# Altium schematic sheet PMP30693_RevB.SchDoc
size 431 x 279 mm; Date: Not shown in title block; ApprovedBy: Not shown in title block; CheckedBy: Not shown in title block; Author: Not shown in title block; CompanyName: Not shown in title block; Engineer: Not shown in title block; Organization: Not shown in title block; Address1: Not shown in title block; Address2: Not shown in title block; Address3: Not shown in title block; Address4: Not shown in title block; DocumentNumber: 2; Revision: Use project parameter SCH_Rev; SheetNumber: 2; SheetTotal: 3; PageSetup: Record=PageOptions¦CenterHorizontal=True¦CenterVertical=True¦PrintScale=1.00¦XCorrection=1.00¦YCorrection=1.00¦PrintKind=0¦BorderSize=5000000¦LeftOffset=0¦BottomOffset=0¦Orientation=2¦PaperLength=1000¦PaperWidth=1000¦Scale=100¦PaperSource=15¦PrintQuality=600¦MediaType=1¦DitherType=10¦PaperKind=Letter¦PrintScaleMode=1
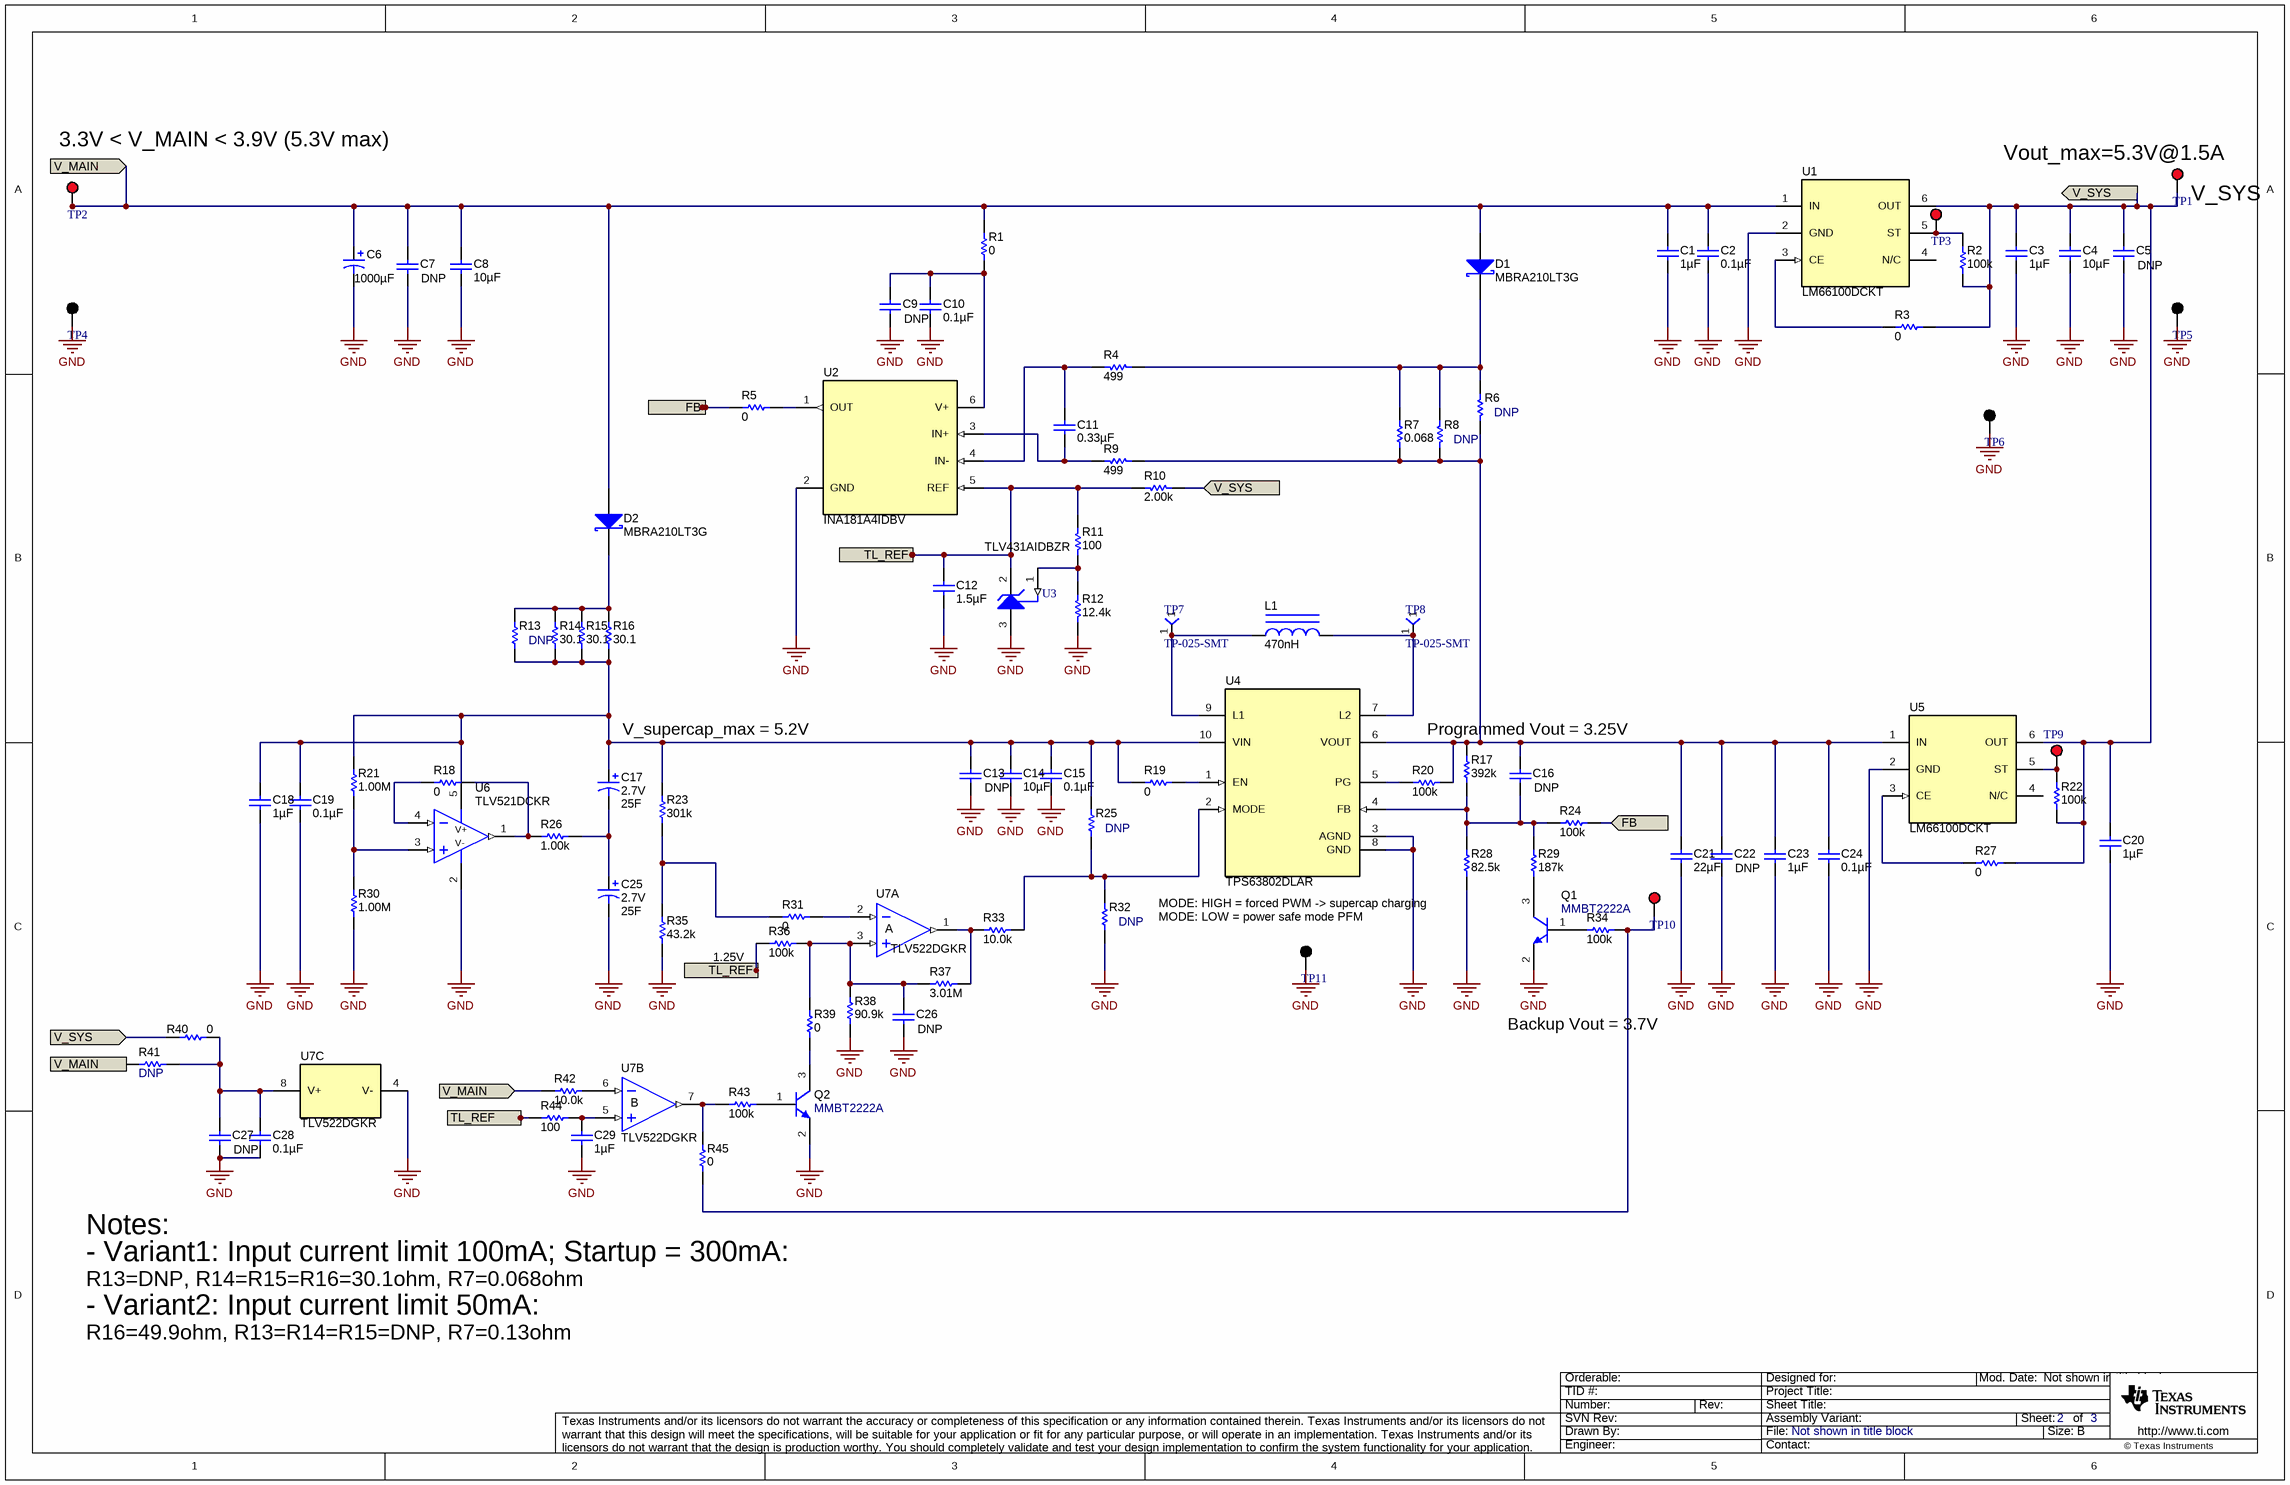
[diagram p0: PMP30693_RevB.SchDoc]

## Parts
C1  ValueDisplayed: 1µF  [0805_HV]  (hidden comment: GRM21BR71A105KA01L)
C2  ValueDisplayed: 0.1µF  [0603]  (hidden comment: GRM188R71H104KA93D)
C3  ValueDisplayed: 1µF  [0805_HV]  (hidden comment: GRM21BR71A105KA01L)
C4  ValueDisplayed: 10µF  [0805_HV]  (hidden comment: GRM21BR70J106KE76L)
C5  DNP  [1206]
C6  ValueDisplayed: 1000µF  [Chemi-Con_1000x2000]  (hidden comment: EKZM160ELL102MJ20S)
C7  DNP  [1206]
C8  ValueDisplayed: 10µF  [0805_HV]  (hidden comment: GRM21BR70J106KE76L)
C9  DNP  [0805]
C10  ValueDisplayed: 0.1µF  [0603]  (hidden comment: GRM188R71H104KA93D)
C11  ValueDisplayed: 0.33µF  [0603]  (hidden comment: C0603C334K4RACTU)
C12  ValueDisplayed: 1.5µF  [0805_HV]  (hidden comment: C0805C155K8RACTU)
C13  DNP  [1206]
C14  ValueDisplayed: 10µF  [0805_HV]  (hidden comment: GRM21BR70J106KE76L)
C15  ValueDisplayed: 0.1µF  [0603]  (hidden comment: GRM188R71H104KA93D)
C16  value DNP  [0603]  (hidden comment: Used in BOM report)
C17  VDC_V: 2.7V  ValueDisplayed: 25F  [SCC_1600x2650]  (hidden comment: SCCU25B256SRB)
C18  ValueDisplayed: 1µF  [0805_HV]  (hidden comment: GRM21BR71A105KA01L)
C19  ValueDisplayed: 0.1µF  [0603]  (hidden comment: GRM188R71H104KA93D)
C20  ValueDisplayed: 1µF  [0805_HV]  (hidden comment: GRM21BR71A105KA01L)
C21  ValueDisplayed: 22µF  [0805_HV]  (hidden comment: CL21B226MQQNNNE)
C22  value DNP  [1206]  (hidden comment: Used in BOM report)
C23  ValueDisplayed: 1µF  [0805_HV]  (hidden comment: GRM21BR71A105KA01L)
C24  ValueDisplayed: 0.1µF  [0603]  (hidden comment: GRM188R71H104KA93D)
C25  VDC_V: 2.7V  ValueDisplayed: 25F  [SCC_1600x2650]  (hidden comment: SCCU25B256SRB)
C26  DNP  [0603]
C27  value DNP  [0805]  (hidden comment: Used in BOM report)
C28  ValueDisplayed: 0.1µF  [0603]  (hidden comment: GRM188R71H104KA93D)
C29  ValueDisplayed: 1µF  [0805_HV]  (hidden comment: C0805C105K8RACTU)
D1  MBRA210LT3G  [SMA]
D2  MBRA210LT3G  [SMA]
L1  ValueDisplayed: 470nH  [XFL4015]  (hidden comment: XFL4015-471MEC)
Q1  MMBT2222A  [SOT-23]
Q2  MMBT2222A  [SOT-23]
R1  ValueDisplayed: 0  [0805_HV]  (hidden comment: CRCW08050000Z0EA)
R2  ValueDisplayed: 100k  [0603]  (hidden comment: CRCW0603100KFKEA)
R3  ValueDisplayed: 0  [0603]  (hidden comment: CRCW06030000Z0EA)
R4  ValueDisplayed: 499  [0603]  (hidden comment: CRCW0603499RFKEA)
R5  ValueDisplayed: 0  [0603]  (hidden comment: CRCW06030000Z0EA)
R6  value DNP  [0805_HV]  (hidden comment: Used in BOM report)
R7  ValueDisplayed: 0.068  [1206]  (hidden comment: ERJ-8BWFR068V)
R8  value DNP  [0805_HV]  (hidden comment: Used in BOM report)
R9  ValueDisplayed: 499  [0603]  (hidden comment: CRCW0603499RFKEA)
R10  ValueDisplayed: 2.00k  [0805_HV]  (hidden comment: CRCW08052K00FKEA)
R11  ValueDisplayed: 100  [0603]  (hidden comment: CRCW0603100RFKEA)
R12  ValueDisplayed: 12.4k  [0603]  (hidden comment: CRCW060312K4FKEA)
R13  value DNP  [2512]  (hidden comment: Used in BOM report)
R14  ValueDisplayed: 30.1  [1206]  (hidden comment: CRCW120630R1FKEA)
R15  ValueDisplayed: 30.1  [1206]  (hidden comment: CRCW120630R1FKEA)
R16  ValueDisplayed: 30.1  [1206]  (hidden comment: CRCW120630R1FKEA)
R17  ValueDisplayed: 392k  [0603]  (hidden comment: CRCW0603392KFKEA)
R18  ValueDisplayed: 0  [0603]  (hidden comment: CRCW06030000Z0EA)
R19  ValueDisplayed: 0  [0603]  (hidden comment: CRCW06030000Z0EA)
R20  ValueDisplayed: 100k  [0603]  (hidden comment: CRCW0603100KFKEA)
R21  ValueDisplayed: 1.00M  [0603]  (hidden comment: CRCW06031M00FKEA)
R22  ValueDisplayed: 100k  [0603]  (hidden comment: CRCW0603100KFKEA)
R23  ValueDisplayed: 301k  [0603]  (hidden comment: CRCW0603301KFKEA)
R24  ValueDisplayed: 100k  [0603]  (hidden comment: CRCW0603100KFKEA)
R25  DNP  [0603]
R26  ValueDisplayed: 1.00k  [0805_HV]  (hidden comment: CRCW08051K00FKEA)
R27  ValueDisplayed: 0  [0603]  (hidden comment: CRCW06030000Z0EA)
R28  ValueDisplayed: 82.5k  [0603]  (hidden comment: CRCW060382K5FKEA)
R29  ValueDisplayed: 187k  [0603]  (hidden comment: CRCW0603187KFKEA)
R30  ValueDisplayed: 1.00M  [0603]  (hidden comment: CRCW06031M00FKEA)
R31  ValueDisplayed: 0  [0603]  (hidden comment: CRCW06030000Z0EA)
R32  DNP  [0603]
R33  ValueDisplayed: 10.0k  [0603]  (hidden comment: CRCW060310K0FKEA)
R34  ValueDisplayed: 100k  [0603]  (hidden comment: CRCW0603100KFKEA)
R35  ValueDisplayed: 43.2k  [0603]  (hidden comment: CRCW060343K2FKEA)
R36  ValueDisplayed: 100k  [0603]  (hidden comment: CRCW0603100KFKEA)
R37  ValueDisplayed: 3.01M  [0603]  (hidden comment: CRCW06033M01FKEA)
R38  ValueDisplayed: 90.9k  [0603]  (hidden comment: CRCW060390K9FKEA)
R39  ValueDisplayed: 0  [0603]  (hidden comment: CRCW06030000Z0EA)
R40  ValueDisplayed: 0  [0805_HV]  (hidden comment: CRCW08050000Z0EA)
R41  DNP  [0805_HV]
R42  ValueDisplayed: 10.0k  [0603]  (hidden comment: CRCW060310K0FKEA)
R43  ValueDisplayed: 100k  [0603]  (hidden comment: CRCW0603100KFKEA)
R44  ValueDisplayed: 100  [0805_HV]  (hidden comment: CRCW0805100RJNEA)
R45  ValueDisplayed: 0  [0603]  (hidden comment: CRCW06030000Z0EA)
TP1  5000  [Keystone5000]  (value not drawn)
TP2  5000  [Keystone5000]  (value not drawn)
TP3  5000  [Keystone5000]  (value not drawn)
TP4  5001  [Keystone5001]  (value not drawn)
TP5  5001  [Keystone5001]  (value not drawn)
TP6  5001  [Keystone5001]  (value not drawn)
TP7  TP-025-SMT  [TP_25MIL-SMT]
TP8  TP-025-SMT  [TP_25MIL-SMT]
TP9  5000  [Keystone5000]  (value not drawn)
TP10  5000  [Keystone5000]  (value not drawn)
TP11  5001  [Keystone5001]  (value not drawn)
U1  LM66100DCKT  [DCK0006A_N]
U2  INA181A4IDBV  [DBV0006A_N]
U3  TLV431AIDBZR  [DBZ0003A_N]
U4  TPS63802DLAR  [DLA0010A]
U5  LM66100DCKT  [DCK0006A_N]
U6  TLV521DCKR  [DCK0005A_N]
U7  TLV522DGKR  [DGK0008A_N]  (parts A,B,C of 3)

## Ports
FB (in), FB (out), TL_REF (in), TL_REF (out), V_MAIN (in), V_SYS (in), V_SYS (out)

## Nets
GND: C1.2 C2.2 C3.2 C4.2 C5.2 C6.2(-) C7.2 C8.2 C9.2 C10.2 C12.2 C13.2 C14.2 C15.2 C18.2 C19.2 C20.2 C21.2 C22.2 C23.2 C24.2 C25.2(-) C26.2 C27.2 C28.2 C29.2 Q1.2(E) Q2.2(E) R12.1 R28.1 R30.1 R32.2 R35.1 R38.1 TP4.1 TP5.1 TP6.1 TP11.1 U1.2(GND) U2.2(GND) U3.3(ANODE) U4.3(AGND) U4.8(GND) U5.2(GND) U6.2(V-) U7.4(V-)
FB: R5.1 R24.2 ; port FB
TL_REF: C12.1 R10.2 R11.2 R44.1 U2.5(REF) U3.2(CATHODE) ; port TL_REF
V_MAIN: C1.1 C2.1 C6.1(+) C7.1 C8.1 D1.2(A) D2.2(A) R1.2 R41.1 R42.1 TP2.1 U1.1(IN) ; port V_MAIN
V_SYS: C3.1 C4.1 C5.1 C20.1 R2.1 R3.1 R10.1 R22.1 R27.1 R40.1 TP1.1 U1.6(OUT) U5.6(OUT) ; port V_SYS
NetC9_1: C9.1 C10.1 R1.1 U2.6(V+)
NetC11_1: C11.1 R9.2 U2.3(IN+)
NetC11_2: C11.2 R4.2 U2.4(IN-)
NetC13_1: C13.1 C14.1 C15.1 C17.1(+) C18.1 C19.1 R13.1 R14.1 R15.1 R16.1 R19.1 R21.2 R23.2 R25.1 U4.10(VIN) U6.5(V+)
NetC16_1: C16.1 C21.1 C22.1 C23.1 C24.1 R6.1 R7.1 R8.1 R9.1 R17.2 R20.2 U4.6(VOUT) U5.1(IN)
NetC16_2: C16.2 R17.1 R24.1 R28.2 R29.2 U4.4(FB)
NetC17_2: C17.2(-) C25.1(+) R26.2
NetC26_1: C26.1 R36.2 R37.1 R38.2 R39.1 U7.3(IN+)
NetC27_1: C27.1 C28.1 R40.2 R41.2 U7.8(V+)
NetC29_1: C29.1 R44.2 U7.5(IN+)
NetD1_1: D1.1(K) R4.1 R6.2 R7.2 R8.2
NetD2_1: D2.1(K) R13.2 R14.2 R15.2 R16.2
NetL1_1: L1.1 TP7.1 U4.9(L1)
NetL1_2: L1.2 TP8.1 U4.7(L2)
NetQ1_1: Q1.1(B) R34.1
NetQ1_3: Q1.3(C) R29.1
NetQ2_1: Q2.1(B) R43.2
NetQ2_3: Q2.3(C) R39.2
NetR2_2: R2.2 TP3.1 U1.5(ST)
NetR3_2: R3.2 U1.3(CE)
NetR5_2: R5.2 U2.1(OUT)
NetR11_1: R11.1 R12.2 U3.1(REF)
NetR18_1: R18.1 U6.4(IN-)
NetR18_2: R18.2 R26.1 U6.1(OUT)
NetR19_2: R19.2 U4.1(EN)
NetR20_1: R20.1 U4.5(PG)
NetR21_1: R21.1 R30.2 U6.3(IN+)
NetR22_2: R22.2 TP9.1 U5.5(ST)
NetR23_1: R23.1 R31.1 R35.2
NetR25_2: R25.2 R32.1 R33.2 U4.2(MODE)
NetR27_2: R27.2 U5.3(CE)
NetR31_2: R31.2 U7.2(IN-)
NetR33_1: R33.1 R37.2 U7.1(OUT)
NetR34_2: R34.2 R45.2 TP10.1
NetR42_2: R42.2 U7.6(IN-)
NetR43_1: R43.1 R45.1 U7.7(OUT)

Not connected (* = marked no-connect by the designer): R36 1; U1 4(N/C); U5 4(N/C)

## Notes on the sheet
- (near TP2) 3.3V < V_MAIN < 3.9V (5.3V max)
- (near TP1) Vout_max=5.3V@1.5A
- (near TP1) V_SYS
- V_supercap_max = 5.2V
- (near R17) Programmed Vout = 3.25V
- MODE: HIGH = forced PWM -> supercap charging
- (near R36) 1.25V
- MODE: LOW = power safe mode PFM
- Backup Vout = 3.7V
- Notes:
- - Variant2: Input current limit 50mA:
- - Variant1: Input current limit 100mA; Startup = 300mA:
- R13=DNP, R14=R15=R16=30.1ohm, R7=0.068ohm
- R16=49.9ohm, R13=R14=R15=DNP, R7=0.13ohm

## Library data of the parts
C1 C3 C18 C20 C23 = GRM21BR71A105KA01L: CAP, CERM, 1 µF, 10 V,+/- 10%, X7R, 0805; Manufacturer: MuRata; Polarized: N; CompType: Capacitor; Value: 1uF; U/M: EA; Cap_F: 0.000001; Tolerance_%: 10; ESR_ohm: 0.007; Value1: 0.007 ohm; Value2: 10V; TaMin_C: -55; TaMax_C: 125; Cap_Case: 0805; SizeArea_mm2: 2.5; SizeAreaWB_mm2: 6.75; SizeX_mm: 2; SizeY_mm: 1.25; SizeZ_mm: 1.45; AEC Category: Q200
C2 C10 C15 C19 C24 C28 = GRM188R71H104KA93D: CAP, CERM, 0.1 µF, 50 V,+/- 10%, X7R, 0603; Manufacturer: MuRata; Polarized: N; CompType: Capacitor; Value: 0.1uF; U/M: EA; Cap_F: 0.0000001; Tolerance_%: 10; VDC_V: 50; Value2: 50V; TaMin_C: -55; TaMax_C: 125; SizeArea_mm2: 1.28; SizeAreaWB_mm2: 4.68; SizeX_mm: 1.6; SizeY_mm: 0.8; SizeZ_mm: 1; AEC Category: Q200; Green_Lifecycle: Active; Green_REACh: Passed
C4 C8 C14 = GRM21BR70J106KE76L: CAP, CERM, 10 µF, 6.3 V,+/- 10%, X7R, 0805; Manufacturer: MuRata; Polarized: N; CompType: Capacitor; Value: 10uF; U/M: EA; Cap_F: 0.00001; Tolerance_%: 10; VDC_V: 6.3; Value2: 6.3V; TaMin_C: -55; TaMax_C: 125; Cap_Case: 0805; SizeArea_mm2: 2.5; SizeAreaWB_mm2: 6.75; SizeX_mm: 2; SizeY_mm: 1.25; SizeZ_mm: 1.45; AEC Category: Q200; Green_Lifecycle: Active; Green_REACh: Passed
C5 C7 C9 C13 C26 = Capacitor: CAP, CERM, xxxF, xxV, [TempCo], xx%, [PackageReference]; Manufacturer: Used in BOM report; Polarized: N; U/M: EA
C6 = EKZE160ELL102MJ20S: CAP, AL, 1000 µF, 16 V, +/- 20%, TH; Manufacturer: Chemi-Con; Polarized: Y; CompType: Capacitor; Value: 1000uF; U/M: EA; Cap_F: 0.001; Tolerance_%: 20; VDC_V: 16; Value2: 16V; IRMS_A: 1.82; TaMin_C: -40; TaMax_C: 105; Cap_Case: 10x20; SizeAreaWB_mm2: 144; SizeArea_mm2: 100; SizeX_mm: 10; SizeZ_mm: 21.5; AEC Category: Q200; AEC Qualified: N
C11 = C0603C334K4RACTU: CAP, CERM, 0.33 µF, 16 V,+/- 10%, X7R, 0603; Manufacturer: Kemet; Polarized: N; CompType: Capacitor; Value: 0.33uF; U/M: EA; Cap_F: 0.00000033; Tolerance_%: 10; VDC_V: 16; Value2: 16V; TaMin_C: -55; TaMax_C: 125; SizeArea_mm2: 1.28; SizeAreaWB_mm2: 4.68; SizeX_mm: 1.6; SizeY_mm: 0.8; SizeZ_mm: 1; AEC Category: Q200; Green_Lifecycle: Active; Green_REACh: Passed
C12 = C0805C155K8RACTU: CAP, CERM, 1.5 µF, 10 V,+/- 10%, X7R, 0805; Manufacturer: Kemet; Polarized: N; CompType: Capacitor; Value: 1.5uF; U/M: EA; Cap_F: 0.0000015; Tolerance_%: 10; ESR_ohm: 0.009; Value1: 0.009 ohm; Value2: 10V; IRMS_A: 12.74; TaMin_C: -55; TaMax_C: 125; Cap_Case: 0805; SizeArea_mm2: 2.5; SizeAreaWB_mm2: 6.75; SizeX_mm: 2; SizeY_mm: 1.25; SizeZ_mm: 1.45; AEC Category: Q200; Green_Lifecycle: Not Set; Green_REACh: Incomplete
C16 C22 C27 = Capacitor: CAP, CERM, xxxF, xxV, [TempCo], xx%, [PackageReference]; Polarized: N; U/M: EA
C17 C25 = CMP-0860272-1: CAP, Electric Double Layer, 25000000 µF, 2.7 V,+30/--10%, 0.027 ohm, TH; Manufacturer: AVX; AEC Qualified: N; Tolerance_%: 30%; SizeArea_mm2: 256; TaMax_C: 65°C; ESR_ohm: 0.027; SizeZ_mm: 26.5; Cap_Case: 16x25mm; CompType: Capacitor; SizeY_mm: 16; SizeAreaWB_mm2: 324; TaMin_C: -40°C; AEC Category: Q200; Polarized: Y; Value: 25000000uF
C21 = CL21B226MQQNNNE: CAP, CERM, 22 µF, 6.3 V,+/- 20%, X7R, 0805; Manufacturer: Samsung Electro-Mechanics; Polarized: N; CompType: Capacitor; Value: 22uF; U/M: EA; Cap_F: 0.000022; Tolerance_%: 20; VDC_V: 6.3; Value2: 6.3V; TaMin_C: -55; TaMax_C: 125; Cap_Case: 0805; SizeArea_mm2: 2.5; SizeAreaWB_mm2: 6.75; SizeX_mm: 2; SizeY_mm: 1.25; SizeZ_mm: 1.45; AEC Category: Q200
C29 = C0805C105K8RACTU: CAP, CERM, 1 µF, 10 V,+/- 10%, X7R, 0805; Manufacturer: Kemet; Polarized: N; CompType: Capacitor; Value: 1uF; U/M: EA; Cap_F: 0.000001; Tolerance_%: 10; ESR_ohm: 0.015; Value1: 0.015 ohm; Value2: 10V; IRMS_A: 8.19; TaMin_C: -55; TaMax_C: 125; Cap_Case: 0805; SizeArea_mm2: 2.5; SizeAreaWB_mm2: 6.75; SizeX_mm: 2; SizeY_mm: 1.25; SizeZ_mm: 1.45; AEC Category: Q200; Green_Lifecycle: Not Set; Green_REACh: Incomplete
D1 D2 = MBRA210LT3G: Diode, Schottky, 10 V, 2 A, SMA; Manufacturer: ON Semiconductor; U/M: EA; Vf_V: 0.35; Value: 10V; Value1: 2A; Value2: 0.35V; Io_A: 2; Vr_V: 10; TJmax_C: 125; RJC_CperW: 22; SizeAreaWB_mm2: 37.3428; SizeArea_mm2: 16.3228; SizeX_mm: 5.59; SizeY_mm: 2.92; SizeZ_mm: 2.87; AEC Category: Q101; Green_Lifecycle: Not Set; Green_REACh: Incomplete
L1 = CMP-0061147-1: Inductor, Shielded, Composite, 470 nH, 3.5 A, 0.0076 ohm, SMD; Manufacturer: Coilcraft; Isat: 3.5A @ 10% inductance drop; Irms: 9.1A @ 20C rise; Green_Lifecycle: Not Set; SizeAreaWB_mm2: 28.09; DCR_ohm: 7.6m; Green_REACh: Incomplete; Value: 470nH; Imax_A: 3.5A; SizeZ_mm: 1.6; SizeX_mm: 4.3; SizeArea_mm2: 18.49; AEC Category: Q200
Q1 Q2 = CMP-0000385-1: Transistor, NPN, 40 V, 0.15 A, SOT-23; Manufacturer: Fairchild Semiconductor; TaMax_C: 150°C; Value2: 300; Value1: 0.15 A; Vcesat1_V: 300mV; SizeX_mm: 2.5; SizeY_mm: 3; TaMin_C: -55°C; IcRated_A: 150mA; CompType: BJT; SizeZ_mm: 1.1; Value: 40 V; SizeArea_mm2: 7.5; NPN: 1; Vceo_V: 40V; PNP: 0; AEC Category: Q101; SizeAreaWB_mm2: 14; U/M: EA
R1 R40 = CRCW08050000Z0EA: RES, 0, 5%, 0.125 W, 0805; Manufacturer: Vishay-Dale; CompType: Resistor; Value: 0; Value_Code: 0000; Tolerance_%: 5; Power_W: 0.125; Value2: 0.125W; VDC_V: 150; TempCo: 200 ppm/C; SizeArea_mm2: 2.5; SizeX_mm: 2; SizeY_mm: 1.25; SizeZ_mm: 1.45; EIA_Code: E24; U/M: EA; AEC Category: Q200; Green_Lifecycle: Active; Green_REACh: Passed
R2 R20 R22 R24 R34 R36 R43 = CRCW0603100KFKEA: RES, 100 k, 1%, 0.1 W, 0603; Manufacturer: Vishay-Dale; CompType: Resistor; Value: 100k; Res_ohm: 100000; Tolerance_%: 1; Power_W: 0.1; Value2: 0.1W; VDC_V: 75; TempCo: 100 ppm/C; SizeArea_mm2: 1.28; SizeX_mm: 1.6; SizeY_mm: 0.8; EIA_Code: E96; U/M: EA; AEC Category: Q200; Green_Lifecycle: Active; Green_REACh: Passed
R3 R5 R18 R19 R27 R31 R39 R45 = CRCW06030000Z0EA: RES, 0, 5%, 0.1 W, 0603; Manufacturer: Vishay-Dale; CompType: Resistor; Value: 0; Value_Code: 0000; Tolerance_%: 5; Power_W: 0.1; Value2: 0.1W; VDC_V: 75; TempCo: 200 ppm/C; SizeArea_mm2: 1.28; SizeX_mm: 1.6; SizeY_mm: 0.8; SizeZ_mm: 1; EIA_Code: E24; U/M: EA; AEC Category: Q200; Green_Lifecycle: Active; Green_REACh: Passed
R4 R9 = CRCW0603499RFKEA: RES, 499, 1%, 0.1 W, 0603; Manufacturer: Vishay-Dale; CompType: Resistor; Value: 499; Value_Code: 499R; Tolerance_%: 1; Power_W: 0.1; Value2: 0.1W; VDC_V: 75; TempCo: 100 ppm/C; SizeArea_mm2: 1.28; SizeX_mm: 1.6; SizeY_mm: 0.8; EIA_Code: E96; U/M: EA; AEC Category: Q200; Green_Lifecycle: Active; Green_REACh: Passed
R6 R8 R13 = Resistor: RES, xxx ohm, x%, xW, [PackageReference]; U/M: EA
R7 = ERJ-8BWFR075V: RES, 0.068, 1%, 0.5 W, 1206; Manufacturer: Panasonic; CompType: Resistor; Value: 0.068; Value_Code: R068; Tolerance_%: 1; Power_W: 0.5; Value2: 0.5W; VDC_V: 0; TempCo: 150 ppm/C; SizeArea_mm2: 5.12; SizeX_mm: 3.2; SizeY_mm: 1.6; SizeZ_mm: 1.35; EIA_Code: E96; U/M: EA; AEC Category: Q200
R10 = CRCW08052K00FKEA: RES, 2.00 k, 1%, 0.125 W, 0805; Manufacturer: Vishay-Dale; CompType: Resistor; Value: 2.00k; Res_ohm: 2000; Value_Code: 2k00; Tolerance_%: 1; Power_W: 0.125; Value2: 0.125W; VDC_V: 150; TempCo: 100 ppm/C; SizeArea_mm2: 2.5; SizeX_mm: 2; SizeY_mm: 1.25; SizeZ_mm: 1.45; EIA_Code: E96; U/M: EA; AEC Category: Q200; Green_Lifecycle: Active; Green_REACh: Passed
R11 = CRCW0603100RFKEA: RES, 100, 1%, 0.1 W, 0603; Manufacturer: Vishay-Dale; CompType: Resistor; Value: 100; Value_Code: 100R; Tolerance_%: 1; Power_W: 0.1; Value2: 0.1W; VDC_V: 75; TempCo: 100 ppm/C; SizeArea_mm2: 1.28; SizeX_mm: 1.6; SizeY_mm: 0.8; EIA_Code: E96; U/M: EA; AEC Category: Q200; Green_Lifecycle: Active; Green_REACh: Passed
R12 = CRCW060312K4FKEA: RES, 12.4 k, 1%, 0.1 W, 0603; Manufacturer: Vishay-Dale; CompType: Resistor; Value: 12.4k; Res_ohm: 12400; Value_Code: 12k4; Tolerance_%: 1; Power_W: 0.1; Value2: 0.1W; VDC_V: 75; TempCo: 100 ppm/C; SizeArea_mm2: 1.28; SizeX_mm: 1.6; SizeY_mm: 0.8; EIA_Code: E96; U/M: EA; AEC Category: Q200; Green_Lifecycle: Active; Green_REACh: Passed
R14-R16 = CRCW120630R1FKEA: RES, 30.1, 1%, 0.25 W, 1206; Manufacturer: Vishay-Dale; CompType: Resistor; Value: 30.1; Value_Code: 30R1; Tolerance_%: 1; Power_W: 0.25; Value2: 0.25W; VDC_V: 200; TempCo: 100 ppm/C; SizeArea_mm2: 5.12; SizeX_mm: 3.2; SizeY_mm: 1.6; SizeZ_mm: 1.35; EIA_Code: E96; U/M: EA; AEC Category: Q200; Green_Lifecycle: Active; Green_REACh: Passed
R17 = CRCW0603392KFKEA: RES, 392 k, 1%, 0.1 W, 0603; Manufacturer: Vishay-Dale; CompType: Resistor; Value: 392k; Res_ohm: 392000; Tolerance_%: 1; Power_W: 0.1; Value2: 0.1W; VDC_V: 75; TempCo: 100 ppm/C; SizeArea_mm2: 1.28; SizeX_mm: 1.6; SizeY_mm: 0.8; EIA_Code: E96; U/M: EA; AEC Category: Q200
R21 R30 = CRCW06031M00FKEA: RES, 1.00 M, 1%, 0.1 W, 0603; Manufacturer: Vishay-Dale; CompType: Resistor; Value: 1.00Meg; Res_ohm: 1000000; Value_Code: 1M00; Tolerance_%: 1; Power_W: 0.1; Value2: 0.1W; VDC_V: 75; TempCo: 100 ppm/C; SizeArea_mm2: 1.28; SizeX_mm: 1.6; SizeY_mm: 0.8; EIA_Code: E96; U/M: EA; AEC Category: Q200; Green_Lifecycle: Active; Green_REACh: Passed
R23 = CRCW0603301KFKEA: RES, 301 k, 1%, 0.1 W, 0603; Manufacturer: Vishay-Dale; CompType: Resistor; Value: 301k; Res_ohm: 301000; Tolerance_%: 1; Power_W: 0.1; Value2: 0.1W; VDC_V: 75; TempCo: 100 ppm/C; SizeArea_mm2: 1.28; SizeX_mm: 1.6; SizeY_mm: 0.8; EIA_Code: E96; U/M: EA; AEC Category: Q200; Green_Lifecycle: Active; Green_REACh: Passed
R25 R32 R41 = Resistor: RES, xxx ohm, x%, xW, [PackageReference]; Manufacturer: Used in BOM report; U/M: EA
R26 = CRCW08051K00FKEA: RES, 1.00 k, 1%, 0.125 W, 0805; Manufacturer: Vishay-Dale; CompType: Resistor; Value: 1.00k; Res_ohm: 1000; Value_Code: 1k00; Tolerance_%: 1; Power_W: 0.125; Value2: 0.125W; VDC_V: 150; TempCo: 100 ppm/C; SizeArea_mm2: 2.5; SizeX_mm: 2; SizeY_mm: 1.25; SizeZ_mm: 1.45; EIA_Code: E96; U/M: EA; AEC Category: Q200; Green_Lifecycle: Active; Green_REACh: Passed
R28 = CRCW060382K5FKEA: RES, 82.5 k, 1%, 0.1 W, 0603; Manufacturer: Vishay-Dale; CompType: Resistor; Value: 82.5k; Res_ohm: 82500; Value_Code: 82k5; Tolerance_%: 1; Power_W: 0.1; Value2: 0.1W; VDC_V: 75; TempCo: 100 ppm/C; SizeArea_mm2: 1.28; SizeX_mm: 1.6; SizeY_mm: 0.8; EIA_Code: E96; U/M: EA; AEC Category: Q200; Green_Lifecycle: Active; Green_REACh: Passed
R29 = CRCW0603187KFKEA: RES, 187 k, 1%, 0.1 W, 0603; Manufacturer: Vishay-Dale; CompType: Resistor; Value: 187k; Res_ohm: 187000; Tolerance_%: 1; Power_W: 0.1; Value2: 0.1W; VDC_V: 75; TempCo: 100 ppm/C; SizeArea_mm2: 1.28; SizeX_mm: 1.6; SizeY_mm: 0.8; EIA_Code: E96; U/M: EA; AEC Category: Q200; Green_Lifecycle: Active; Green_REACh: Passed
R33 R42 = CRCW060310K0FKEA: RES, 10.0 k, 1%, 0.1 W, 0603; Manufacturer: Vishay-Dale; CompType: Resistor; Value: 10.0k; Res_ohm: 10000; Value_Code: 10k0; Tolerance_%: 1; Power_W: 0.1; Value2: 0.1W; VDC_V: 75; TempCo: 100 ppm/C; SizeArea_mm2: 1.28; SizeX_mm: 1.6; SizeY_mm: 0.8; EIA_Code: E96; U/M: EA; AEC Category: Q200; Green_Lifecycle: Active; Green_REACh: Passed
R35 = CRCW060343K2FKEA: RES, 43.2 k, 1%, 0.1 W, 0603; Manufacturer: Vishay-Dale; CompType: Resistor; Value: 43.2k; Res_ohm: 43200; Value_Code: 43k2; Tolerance_%: 1; Power_W: 0.1; Value2: 0.1W; VDC_V: 75; TempCo: 100 ppm/C; SizeArea_mm2: 1.28; SizeX_mm: 1.6; SizeY_mm: 0.8; EIA_Code: E96; U/M: EA; AEC Category: Q200; Green_Lifecycle: Active; Green_REACh: Passed
R37 = CRCW06033M01FKEA: RES, 3.01 M, 1%, 0.1 W, 0603; Manufacturer: Vishay-Dale; CompType: Resistor; Value: 3.01Meg; Res_ohm: 3010000; Value_Code: 3M01; Tolerance_%: 1; Power_W: 0.1; Value2: 0.1W; VDC_V: 75; TempCo: 100 ppm/C; SizeArea_mm2: 1.28; SizeX_mm: 1.6; SizeY_mm: 0.8; EIA_Code: E96; U/M: EA; AEC Category: Q200; Green_Lifecycle: Active; Green_REACh: Passed
R38 = CRCW060390K9FKEA: RES, 90.9 k, 1%, 0.1 W, 0603; Manufacturer: Vishay-Dale; CompType: Resistor; Value: 90.9k; Res_ohm: 90900; Value_Code: 90k9; Tolerance_%: 1; Power_W: 0.1; Value2: 0.1W; VDC_V: 75; TempCo: 100 ppm/C; SizeArea_mm2: 1.28; SizeX_mm: 1.6; SizeY_mm: 0.8; EIA_Code: E96; U/M: EA; AEC Category: Q200; Green_Lifecycle: Active; Green_REACh: Passed
R44 = CRCW0805100RJNEA: RES, 100, 5%, 0.125 W, 0805; Manufacturer: Vishay-Dale; CompType: Resistor; Value: 100; Value_Code: 100R; Tolerance_%: 5; Power_W: 0.125; Value2: 0.125W; VDC_V: 150; TempCo: 200 ppm/C; SizeArea_mm2: 2.5; SizeX_mm: 2; SizeY_mm: 1.25; SizeZ_mm: 1.45; EIA_Code: E24; U/M: EA; AEC Category: Q200
TP1-TP3 TP9 TP10 = 5000: Test Point, Miniature, Red, TH; Manufacturer: Keystone; CompType: Test Point Loop; ContactFinish: Silver; Green_Lifecycle: Active; Green_REACh: Passed
TP4-TP6 TP11 = 5001: Test Point, Miniature, Black, TH; Manufacturer: Keystone; CompType: Test Point Loop; ContactFinish: Silver; Green_Lifecycle: Active; Green_REACh: Passed
TP7 TP8 = TP-025-SMT: Test Point, O.025"; Manufacturer: STD; Value: STD
U1 U5 = CMP-0085652-1: +/-6V, Low IQ Ideal Diode with Input Polarity Protection, DCK0006A (SOT-SC70-6); Alternate Manufacturer: Texas Instruments; Alternate PartNumber: LM66100DCKR; SizeArea_mm2: 4.2; AEC Qualified: N; SizeAreaWB_mm2: 9.3; AEC Category: Q200; CompType: IC; SizeZ_mm: 1.1; SizeY_mm: 2; SizeX_mm: 2.1
U2 = CMP-0013228-2: Bidirectional, Low- and High-Side Measurement, Multichannel, Voltage Output, Current-Sense Amplifier, DBV0006A (SOT-6); Manufacturer: Texas Instruments; SizeX_mm: 2.8; SizeY_mm: 2.9; CompType: IC; SizeZ_mm: 1.45; SizeArea_mm2: 8.12; SizeAreaWB_mm2: 14.82; U/M: EA
U3 = CMP-0033044-1: Low Voltage Adjustable Precision Shunt Regulator, 39 ppm / degC, 15 mA, -40 to 85 degC, 3-pin SOT-23 (DBZ), Green (RoHS & no Sb/Br); Manufacturer: Texas Instruments; VO Adj(Max)(V): 6; Temp Coeff(Max)(ppm/ degree C): 129; Min Iz for Regulation(uA): 80; Iout/Iz(Max)(mA): 15; Rating: Catalog; VO Adj(Min)(V): 1.24; Initial Accuracy @ 25/deg C(%): 1; SubFamily: Shunt Voltage Reference; Temp Coeff(Typ)(ppm/ degree C): 39
U4 = CMP-0076712-5: High Current, High Efficiency Single Inductor Buck-Boost Converter, DLA0010A (VSON-HR-10); Alternate Manufacturer: Texas Instruments; Alternate PartNumber: TPS63802DLAT; SizeAreaWB_mm2: 12.0; SizeY_mm: 3.0; AEC Category: Q200; SizeArea_mm2: 6.0; CompType: IC; AEC Qualified: N; SizeX_mm: 2.0; SizeZ_mm: 1.0
U6 = CMP-0084062-1: 350-nA Nanopower, Single, RRIO, CMOS Input, Operational Amplifier for Cost-Sensitive Systems, DCK0005A (SOT-SC70-5); Manufacturer: Texas Instruments; Alternate PartNumber: TLV521DCKT; Rating: Catalog; SizeAreaWB_mm2: 9.3; SizeArea_mm2: 4.2; AEC Qualified: N; AEC Category: Q200; SizeZ_mm: 1.1; SizeY_mm: 2; CompType: IC; SizeX_mm: 2.1
U7 = CMP-0860538-1: 500-nA Nanopower, Dual, RRIO, CMOS-Input Operational Amplifier for Cost-Sensitive Systems, DGK0008A (VSSOP-8); Alternate Manufacturer: Texas Instruments; Alternate PartNumber: TLV522DGKT; SizeZ_mm: 1.1; Rating: Catalog; SizeY_mm: 3; AEC Qualified: N; CompType: IC; AEC Category: Q200; SizeX_mm: 4.9; SizeAreaWB_mm2: 23.6; SizeArea_mm2: 14.7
